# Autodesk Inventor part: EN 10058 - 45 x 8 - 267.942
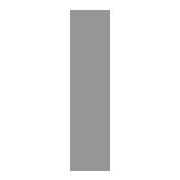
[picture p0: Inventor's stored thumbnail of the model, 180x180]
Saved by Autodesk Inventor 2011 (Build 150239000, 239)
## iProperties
_CCFamilyMember: 49
_CCFamilyDisplayName: DIN EN 10058 - Hot rolled flat steel bars for general purposes
_FrameMemberDoc: Frame Member File
_Version: 15.0.0
_GetPNFromCC: 1
Created: 2010-02
Part Number: EN 10058 - 45 x 8 - 267.942
Material: Steel, Mild
Description: flat steel bar 45*8
Document SubType Name: Modeling
Standard: DIN
Designer: PC
Standard Revision: 2004
Standards Organization: DIN
Language: en-US
Size Designation: 45 x 8
Categories: <MemberInstance><Categories><Category DisplayName="Structural Shapes" InternalName="089c4875-fa83-4c05-b084-43b9cc11f5ed" Mnemonic="GRDR"><CategoryParameter Dis
Stock Number: 45 x 8
Density: 7.86 g/cm^3
IsCustomPart: 1
G_L: 267.942 mm
G_W: 8.000 mm
G_H: 45.000 mm
+9B0C2B2B-68E7-4828-8D7A-98A0C83C7149+CUTDETAIL1: Cut
Author: PC
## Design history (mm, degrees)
node "Start plane"
node "End plane"
sketch "Sketch"
  geometry: L1 (4, -22.5)-(-4, -22.5); L2 (-4, -22.5)-(-4, 22.5); L3 (-4, 22.5)-(4, 22.5); L4 (4, 22.5)-(4, -22.5); L5 (-6, 0)-(8, 0); L6 (0, -30)-(0, 40); L7 (0, 54)-(0, -44) reference; L8 (-9.2, 0)-(13.2, 0) reference
  constraints: 12 end point, 2 collinear, 2 parallel, 1 horizontal, 1 perpendicular
  dimensions: "d0" = 45 distance between parallel lines of L3 L1 (= G_W); "d1" = 8 distance between parallel lines of L4 L2 (= G_H); "d4" = 4 distance between parallel lines of L6 L4 (= 0.5 x d1); "d5" = 22.5 distance between parallel lines of L5 L3 (= 0.5 x d0)
extrude "Body" new body sketch "Sketch" stored distance "d2" = 267.94229 (= G_L); taper "d3" = 0 deg
node "Driven Length"
  sketch "Sketch3"
    geometry: L1 (0, 0)-(10, 0) reference
    constraints: 2 end point, 1 horizontal
  workplane "Work Plane3"
  sketch "Sketch4"
    geometry: L1 (-2, 0)-(12, 0) reference; L2 (-2, 267.942)-(12, 267.942) reference
    dimensions: "d9" = 267.94229 distance between parallel lines of L1 L2 (derived)
workplane "Work Plane4"
split "Split1"
body "Solid1"
other parameters: "G_W" = 45 [user parameter; used in 1 equation term], "G_H" = 8 [user parameter; used in 1 equation term], "G_L" = 267.94229 (= d9) [user parameter; used in 1 equation term], "G_OFFSET_START" = 0 [user parameter; used in 1 equation term], "G_OFFSET_END" = 167.94229 [user parameter; used in 1 equation term], "d6" = 0 (computed from G_OFFSET_START), "d7" = 267.94229 (= G_OFFSET_END + B_L), "d8" = 90 deg, "MAS" = 0.283 [user parameter]
